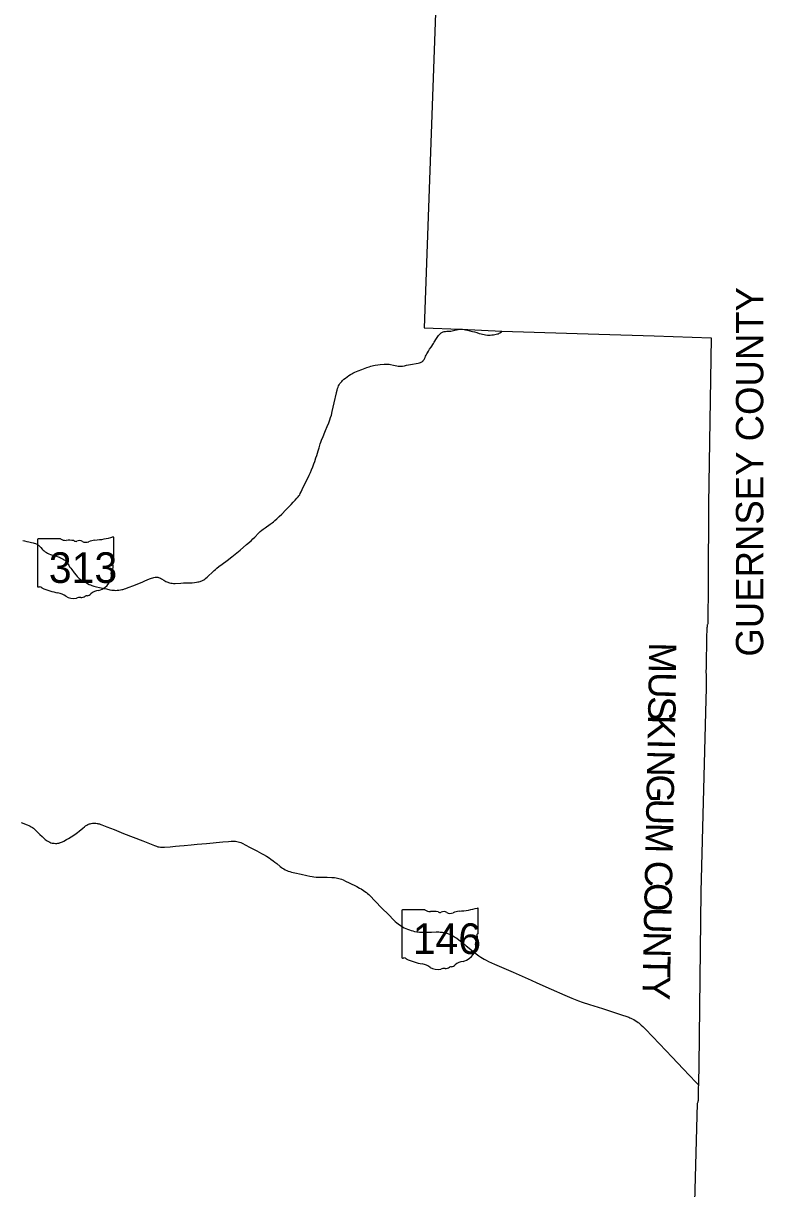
# Model space of a CAD drawing. Extents: x 1913970 to 2287843, y 78841 to 799733.
# Drawn here: x 2185120 to 2212197, y 667975 to 710619 of the extents above; entities that cross this region are included whole.
import ezdxf

# ---------------------------------------------------------------- set-up
doc = ezdxf.new("R2010")
doc.units = 0
for name, color, linetype in [('GM_X_County', 7, 'Continuous'), ('GM_X_County_Text', 7, 'Continuous'), ('GM_X_State_Location', 7, 'Continuous'), ('GM_X_State_Route', 7, 'Continuous'), ('GM_X_State_Shield', 7, 'Continuous')]:
    doc.layers.add(name, color=color, linetype=linetype)

msp = doc.modelspace()

# ---------------------------------------------------------------- linework, layer by layer
at = {"layer": 'GM_X_County'}
msp.add_lwpolyline([(2200352, 715403), (2199774, 699473), (2201089, 699432), (2201116, 699431), (2201134, 699430), (2202626, 699355), (2206162, 699242), (2208195, 699179), (2210280, 699112), (2210180, 693025), (2210170, 690133), (2210151, 688640), (2210142, 688621), (2210136, 688604), (2210132, 688585), (2210129, 688569), (2210127, 688554), (2210125, 688537), (2210121, 688494), (2210119, 688456), (2210115, 688374), (2210113, 688325), (2210111, 688276), (2210105, 688097), (2210105, 688073), (2210104, 688049), (2210104, 688032), (2210104, 687966), (2210103, 687884), (2210100, 687721), (2210097, 687522), (2210094, 687247), (2210091, 687121), (2210089, 687031), (2210086, 686899), (2210089, 686771), (2210091, 686640), (2210092, 686493), (2210092, 686411), (2210092, 686298), (2210089, 686216), (2210085, 685941), (2210084, 685916), (2210083, 685902), (2210082, 685889), (2210079, 685870), (2209901, 678842), (2209827, 672479), (2209818, 671863), (2209815, 671768), (2209806, 671695), (2209803, 671676), (2209799, 671617), (2209797, 671558), (2209797, 671513), (2209798, 671434), (2209800, 671342), (2209798, 671257), (2209795, 671202), (2209790, 671166), (2209785, 671141), (2209779, 671122), (2209765, 671089), (2209653, 667025)], dxfattribs=at)
at = {"layer": 'GM_X_State_Route'}
for points in [[(2196811, 697558), (2196847, 697592), (2196898, 697633), (2196964, 697683), (2197031, 697730), (2197086, 697766), (2197129, 697791), (2197172, 697814), (2197247, 697848), (2197369, 697898), (2197505, 697953), (2197689, 698025), (2197766, 698053), (2197828, 698074), (2197876, 698088), (2197924, 698099), (2197988, 698111), (2198086, 698123), (2198167, 698132), (2198314, 698148), (2198363, 698152), (2198412, 698152), (2198462, 698150), (2198495, 698146), (2198543, 698137), (2198655, 698110), (2198719, 698096), (2198783, 698084), (2198831, 698077), (2198864, 698074), (2198896, 698072), (2198945, 698072), (2198993, 698077), (2199057, 698089), (2199138, 698105), (2199203, 698117), (2199358, 698146), (2199483, 698171), (2199564, 698188), (2199611, 698198), (2199642, 698208), (2199671, 698221), (2199699, 698236), (2199713, 698245), (2199738, 698266), (2199749, 698277), (2199760, 698289), (2199770, 698302), (2199779, 698315), (2199794, 698343), (2199813, 698388), (2199832, 698433), (2199851, 698479), (2199872, 698523), (2199897, 698566), (2199933, 698621), (2199979, 698689), (2200034, 698770), (2200122, 698908), (2200148, 698950), (2200236, 699088), (2200281, 699157), (2200309, 699197), (2200341, 699235), (2200364, 699259), (2200389, 699281), (2200402, 699291), (2200430, 699309), (2200445, 699316), (2200475, 699328), (2200507, 699338), (2200540, 699344), (2200556, 699346), (2200605, 699348), (2200655, 699349), (2200704, 699352), (2200752, 699357), (2200800, 699365), (2200847, 699376), (2200901, 699391), (2200942, 699402), (2200962, 699407)], [(2200962, 699407), (2200977, 699412), (2201023, 699420)], [(2201023, 699420), (2201063, 699427), (2201090, 699429), (2201117, 699428), (2201135, 699427), (2201162, 699424), (2201186, 699421), (2201248, 699411), (2201297, 699401)], [(2201297, 699401), (2201369, 699388), (2201455, 699370), (2201551, 699347), (2201615, 699329), (2201709, 699299), (2201787, 699274), (2201866, 699252), (2201914, 699241), (2201978, 699228), (2202027, 699220), (2202092, 699213), (2202141, 699210), (2202190, 699210), (2202256, 699214), (2202321, 699220), (2202370, 699228), (2202418, 699238), (2202465, 699251), (2202495, 699262), (2202505, 699268), (2202524, 699277), (2202551, 699295), (2202604, 699333), (2202627, 699353)], [(2191499, 690176), (2191539, 690184), (2191587, 690195), (2191607, 690201), (2191618, 690204), (2191648, 690215), (2191678, 690229), (2191720, 690253), (2191761, 690280), (2191800, 690310), (2191849, 690353), (2191909, 690408), (2192015, 690511), (2192097, 690591), (2192145, 690636), (2192195, 690678), (2192273, 690739), (2192391, 690827), (2192574, 690965), (2192742, 691097), (2193047, 691346), (2193286, 691545), (2193448, 691683), (2193520, 691750), (2193590, 691819), (2193726, 691961), (2193785, 692018), (2193847, 692073), (2193898, 692114), (2193964, 692163), (2194153, 692293), (2194220, 692340), (2194273, 692379), (2194323, 692421), (2194395, 692487), (2194478, 692567), (2194571, 692659), (2194721, 692810), (2194829, 692920), (2194920, 693012), (2194991, 693091), (2195064, 693169), (2195127, 693238), (2195170, 693288), (2195200, 693327), (2195227, 693367), (2195250, 693410), (2195277, 693469), (2195317, 693559), (2195576, 694090), (2195618, 694178), (2195664, 694283), (2195708, 694389), (2195749, 694496), (2195782, 694589), (2195822, 694713), (2195852, 694807), (2195876, 694887), (2195904, 694979), (2195937, 695089), (2195979, 695234), (2196000, 695292), (2196030, 695368), (2196088, 695504), (2196152, 695655), (2196202, 695776), (2196212, 695802), (2196238, 695868), (2196292, 696005), (2196332, 696112), (2196357, 696190), (2196385, 696284), (2196417, 696412), (2196489, 696731), (2196571, 697099), (2196573, 697104), (2196595, 697195), (2196614, 697258), (2196630, 697305), (2196650, 697350), (2196674, 697394), (2196701, 697435), (2196732, 697474), (2196764, 697512), (2196799, 697547), (2196811, 697558)], [(2185098, 691688), (2185163, 691676), (2185243, 691660), (2185323, 691644), (2185419, 691624), (2185483, 691609), (2185523, 691598), (2185562, 691585), (2185593, 691573), (2185624, 691557), (2185651, 691540), (2185675, 691519), (2185700, 691498), (2185724, 691475), (2185757, 691439), (2185812, 691378), (2185847, 691344), (2185884, 691312), (2185924, 691283), (2185965, 691257), (2186007, 691233), (2186051, 691211), (2186111, 691184), (2186156, 691167), (2186203, 691153), (2186330, 691118), (2186393, 691099), (2186439, 691082), (2186484, 691063), (2186529, 691041), (2186580, 691013), (2186614, 690991), (2186641, 690971), (2186666, 690949), (2186689, 690925), (2186709, 690900), (2186745, 690845), (2186780, 690790), (2186815, 690736), (2186853, 690683), (2186893, 690631), (2186985, 690515), (2187054, 690424), (2187095, 690373), (2187116, 690349), (2187139, 690326), (2187164, 690305), (2187204, 690277), (2187273, 690232), (2187357, 690183), (2187469, 690119), (2187531, 690089), (2187575, 690069), (2187621, 690052), (2187699, 690028), (2187794, 690002), (2187905, 689975), (2187969, 689960), (2188081, 689935), (2188161, 689919), (2188290, 689892), (2188354, 689881), (2188403, 689875), (2188452, 689871), (2188500, 689870), (2188549, 689873), (2188614, 689880), (2188679, 689889), (2188726, 689899), (2188761, 689905), (2188797, 689914), (2188817, 689921), (2188868, 689939), (2188956, 689969), (2189161, 690042), (2189251, 690079), (2189401, 690144), (2189492, 690182), (2189567, 690214), (2189733, 690285), (2189810, 690315), (2189857, 690331), (2189889, 690339), (2189938, 690347), (2189971, 690349), (2190004, 690349), (2190037, 690346), (2190070, 690339), (2190101, 690328), (2190132, 690315), (2190175, 690291), (2190260, 690241), (2190330, 690199), (2190373, 690177), (2190403, 690163), (2190433, 690153), (2190464, 690144), (2190512, 690135), (2190561, 690129), (2190610, 690126), (2190675, 690126), (2190878, 690135), (2190983, 690139), (2191115, 690139), (2191226, 690142), (2191296, 690148), (2191378, 690156), (2191459, 690168), (2191499, 690176)], [(2185044, 681370), (2185260, 681292), (2185321, 681267), (2185366, 681245), (2185409, 681221), (2185450, 681193), (2185489, 681163), (2185538, 681120), (2185728, 680938), (2185811, 680859), (2185886, 680787), (2185923, 680753), (2185955, 680730), (2185996, 680700), (2186037, 680676), (2186086, 680653), (2186132, 680636), (2186177, 680624), (2186214, 680618), (2186251, 680613), (2186295, 680611), (2186343, 680612), (2186380, 680616), (2186420, 680622), (2186442, 680627), (2186453, 680630), (2186482, 680638), (2186519, 680652), (2186559, 680670), (2186603, 680696), (2186703, 680752), (2186774, 680793), (2186872, 680852), (2186968, 680914), (2187049, 680968), (2187101, 681007), (2187165, 681058), (2187295, 681170), (2187357, 681221), (2187398, 681251), (2187438, 681276), (2187476, 681296), (2187506, 681311), (2187536, 681321), (2187568, 681331), (2187602, 681339), (2187653, 681347), (2187698, 681350), (2187734, 681350), (2187773, 681348), (2187817, 681344), (2187847, 681338), (2187875, 681331), (2187903, 681322), (2187961, 681302), (2187992, 681291), (2188179, 681216), (2188437, 681113), (2188696, 681012), (2188788, 680976), (2189490, 680700), (2189734, 680604), (2189917, 680531), (2189994, 680504), (2190041, 680490), (2190089, 680479), (2190137, 680472), (2190169, 680469), (2190218, 680468), (2190283, 680471), (2190496, 680488), (2190594, 680497), (2190691, 680507), (2190838, 680521), (2191001, 680536), (2191263, 680560), (2191475, 680578), (2191818, 680610), (2192422, 680664), (2192618, 680682), (2192717, 680688), (2192782, 680691), (2192832, 680690), (2192881, 680686), (2192930, 680678), (2192979, 680668), (2193026, 680654), (2193072, 680637), (2193118, 680616), (2193393, 680471), (2193540, 680398), (2193656, 680337), (2193830, 680245), (2193901, 680205), (2194012, 680140), (2194110, 680080), (2194178, 680035), (2194258, 679977), (2194323, 679927), (2194386, 679875), (2194509, 679768), (2194560, 679727), (2194600, 679699), (2194642, 679674), (2194699, 679643), (2194758, 679616), (2194804, 679598), (2194865, 679577), (2194928, 679560), (2195056, 679530), (2195279, 679479), (2195487, 679432), (2195599, 679409), (2195680, 679395), (2195745, 679386), (2195826, 679379), (2195890, 679377), (2195941, 679375), (2196236, 679369), (2196400, 679363), (2196498, 679357), (2196564, 679351), (2196613, 679343), (2196661, 679331), (2196708, 679317), (2196754, 679299), (2196814, 679272), (2196903, 679229), (2197035, 679164), (2197315, 679027), (2197418, 678975), (2197475, 678942), (2197558, 678890), (2197612, 678852), (2197665, 678813), (2197703, 678781), (2197751, 678736), (2198027, 678456), (2198200, 678280), (2198511, 677966), (2198638, 677837), (2198708, 677769), (2198722, 677756), (2198777, 677706), (2198827, 677665), (2198880, 677626), (2198934, 677589), (2198990, 677555), (2199047, 677523), (2199106, 677495), (2199166, 677470), (2199243, 677442), (2199305, 677422), (2199368, 677405), (2199432, 677391), (2199513, 677377), (2199561, 677371), (2199610, 677367), (2199692, 677364), (2199987, 677365), (2200051, 677367), (2200215, 677369), (2200264, 677369), (2200316, 677368), (2200363, 677366), (2200405, 677364), (2200451, 677358), (2200495, 677352), (2200532, 677344), (2200573, 677333), (2200605, 677324), (2200667, 677300), (2200729, 677276), (2200774, 677255), (2200832, 677224), (2200889, 677191), (2200930, 677165), (2200970, 677137), (2201048, 677078), (2201202, 676956), (2201318, 676864), (2201420, 676782), (2201638, 676608), (2201781, 676497), (2201848, 676450), (2201916, 676406), (2201973, 676373), (2202045, 676335), (2202134, 676293), (2202358, 676192), (2203034, 675894), (2203694, 675603), (2203904, 675509), (2204429, 675278), (2204925, 675060), (2205180, 674948), (2205301, 674898), (2205424, 674852), (2205563, 674803), (2205828, 674716), (2206296, 674566), (2206999, 674338), (2207186, 674276), (2207224, 674262), (2207266, 674247), (2207305, 674231), (2207343, 674215), (2207384, 674196), (2207442, 674165), (2207499, 674132), (2207554, 674096), (2207608, 674058), (2207634, 674038), (2207659, 674017), (2207722, 673963), (2207781, 673907), (2207873, 673813), (2208381, 673277), (2208845, 672790), (2209252, 672362), (2209715, 671875), (2209786, 671801), (2209816, 671766)]]:
    msp.add_lwpolyline(points, dxfattribs=at)
at = {"layer": 'GM_X_State_Shield'}
for p, q in [((2185634, 691723), (2185634, 690022)), ((2186482, 691752), (2185661, 691752)), ((2188435, 690904), (2188435, 691794)), ((2188435, 690904), (2188435, 690904)), ((2198959, 678145), (2198959, 676444)), ((2199807, 678175), (2198986, 678175)), ((2201760, 677327), (2201760, 678217)), ((2201760, 677327), (2201760, 677327))]:
    msp.add_line(p, q, dxfattribs=at)
for centre, major_axis, start_param, end_param in [((2185666, 691726), (32.5, 0), 1.712693, 3.28349), ((2186677, 691949), (315, 0), 4.042523, 4.731795), ((2186782, 690797), (1130, 0), 1.404758, 1.657858), ((2187171, 691539), (189, 0), 0.950623, 2.079405), ((2187816, 691232), (598, 0), 1.699011, 2.107814), ((2187437, 694071), (2971, 0), 4.814394, 5.042369), ((2188404, 691798), (31.2, 0), 6.141152, 7.989035), ((2187038, 691735), (90.8, 0), 3.836095, 5.185415), ((2187415, 691808), (227, 0), 4.081561, 5.145723), ((2188428, 690839), (48.3, 0), 1.883978, 3.671073), ((2188402, 690901), (33.4, 0), 5.05454, 6.418171), ((2187604, 690419), (743, 0), 5.101752, 6.440018), ((2188547, 690532), (211, 0), 2.387724, 3.262537), ((2188121, 690726), (290, 0), 5.934695, 6.695948), ((2185666, 690018), (32.7, 0), 3.00124, 4.508301), ((2185671, 690192), (250, 0), 4.665946, 4.897461), ((2185722, 689923), (90.1, 0), 0.519207, 1.627899), ((2186860, 691452), (2146, 0), 4.195997, 4.488961), ((2186220, 689257), (671, 0), 0.823519, 1.323587), ((2186946, 689915), (426, 0), 4.026481, 4.996735), ((2187192, 689327), (350, 0), 1.495662, 1.94098), ((2187223, 689788), (227, 0), 4.691044, 5.507374), ((2187429, 689623), (63.9, 0), 1.147584, 2.315152), ((2187401, 689857), (240, 0), 4.937069, 5.64225), ((2187917, 689544), (407, 0), 1.647645, 2.488434), ((2198991, 678149), (32.5, 0), 1.712693, 3.28349), ((2200002, 678372), (315, 0), 4.042523, 4.731795), ((2200106, 677220), (1130, 0), 1.404758, 1.657858), ((2200363, 678158), (90.8, 0), 3.836095, 5.185415), ((2200496, 677961), (189, 0), 0.950623, 2.079405), ((2200740, 678231), (227, 0), 4.081561, 5.145723), ((2201141, 677655), (598, 0), 1.699011, 2.107814), ((2200762, 680494), (2971, 0), 4.814394, 5.042369), ((2201729, 678221), (31.2, 0), 6.141152, 7.989035), ((2201753, 677262), (48.3, 0), 1.883978, 3.671073), ((2201446, 677149), (290, 0), 5.934695, 6.695948), ((2201727, 677324), (33.4, 0), 5.05454, 6.418171), ((2200929, 676841), (743, 0), 5.101752, 6.440018), ((2201872, 676955), (211, 0), 2.387724, 3.262537), ((2198991, 676441), (32.7, 0), 3.00124, 4.508301), ((2198996, 676615), (250, 0), 4.665946, 4.897461), ((2199047, 676346), (90.1, 0), 0.519207, 1.627899), ((2200185, 677875), (2146, 0), 4.195997, 4.488961), ((2199545, 675680), (671, 0), 0.823519, 1.323587), ((2200271, 676338), (426, 0), 4.026481, 4.996735), ((2200517, 675750), (350, 0), 1.495662, 1.94098), ((2200548, 676210), (227, 0), 4.691044, 5.507374), ((2200754, 676046), (63.9, 0), 1.147584, 2.315152), ((2200726, 676279), (240, 0), 4.937069, 5.64225), ((2201242, 675967), (407, 0), 1.647645, 2.488434)]:
    msp.add_ellipse(centre, major_axis=major_axis, ratio=0.8, start_param=start_param, end_param=end_param, dxfattribs=at)

# ---------------------------------------------------------------- texts
at = {"layer": 'GM_X_County_Text'}
for s, rotation, p in [('GUERNSEY COUNTY', 90, (2212182, 687445)), ('M', 269.5558, (2208002, 687966)), ('U', 269.1779, (2207994, 686881)), ('S', 269.0462, (2207981, 685997)), ('K', 268.9125, (2207970, 685320)), ('I', 268.8718, (2207953, 684436)), ('N', 268.856, (2207945, 684027)), ('G', 268.8538, (2207927, 683143)), ('U', 268.8516, (2207910, 682258)), ('M', 268.853, (2207892, 681374)), ('C', 268.8539, (2207864, 679984)), ('O', 268.8516, (2207848, 679170)), ('U', 268.8536, (2207830, 678286)), ('N', 268.8538, (2207812, 677402)), ('T', 268.8531, (2207795, 676518)), ('Y', 268.8516, (2207780, 675770))]:
    msp.add_text(s, height=1000, rotation=rotation, dxfattribs=at).set_placement(p)
at = {"layer": 'GM_X_State_Location'}
for s in ['s', 'r']:
    msp.add_text(s, height=1, dxfattribs=at).set_placement((2200579, 677215))
msp.add_text('146', height=1, rotation=0, dxfattribs=at).set_placement((2200226, 677143))
at = {"layer": 'GM_X_State_Shield'}
for s, p in [('313', (2186054, 690141)), ('146', (2199362, 676564))]:
    msp.add_text(s, height=1120.7, dxfattribs=at).set_placement(p)

doc.saveas('drawing.dxf')
